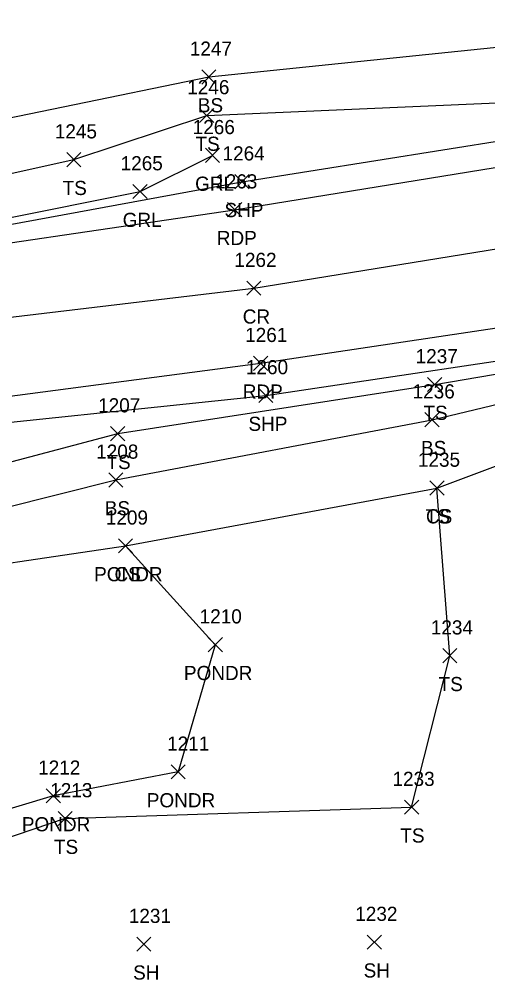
# Model space of a CAD drawing. Extents: x 1497084 to 1499861, y 734741 to 735567.
# Drawn here: x 1498420.9 to 1498487, y 735226.4 to 735362.1 of the extents above; entities that cross this region are included whole.
import ezdxf

# ---------------------------------------------------------------- set-up
doc = ezdxf.new("R2010")
doc.units = 0
for name, color, linetype in [('L_A', 7, 'Continuous'), ('L_I', 7, 'Continuous'), ('L_TIC', 7, 'Continuous'), ('LAWE', 7, 'Continuous'), ('LELB', 7, 'Continuous'), ('P_A', 7, 'Continuous'), ('P_I', 7, 'Continuous'), ('P_TIC', 7, 'Continuous'), ('PET', 7, 'Continuous'), ('PRC', 7, 'Continuous'), ('PSP', 7, 'Continuous'), ('R_A', 7, 'Continuous'), ('R_I', 7, 'Continuous'), ('R_TIC', 7, 'Continuous'), ('RGR', 7, 'Continuous')]:
    doc.layers.add(name, color=color, linetype=linetype)

msp = doc.modelspace()

# ---------------------------------------------------------------- linework, layer by layer
at = {"layer": 'L_TIC'}
for points in [[(1498446.67, 735352.97), (1498448.67, 735354.97)], [(1498448.67, 735352.97), (1498446.67, 735354.97)], [(1498446.37, 735347.53), (1498448.37, 735349.53)], [(1498448.37, 735347.53), (1498446.37, 735349.53)], [(1498427.62, 735341.29), (1498429.62, 735343.29)], [(1498429.62, 735341.29), (1498427.62, 735343.29)], [(1498478.54, 735309.53), (1498480.54, 735311.53)], [(1498480.54, 735309.53), (1498478.54, 735311.53)], [(1498478.17, 735304.56), (1498480.17, 735306.56)], [(1498480.17, 735304.56), (1498478.17, 735306.56)], [(1498433.81, 735302.59), (1498435.81, 735304.59)], [(1498435.81, 735302.59), (1498433.81, 735304.59)], [(1498433.54, 735296.05), (1498435.54, 735298.05)], [(1498435.54, 735296.05), (1498433.54, 735298.05)], [(1498478.86, 735294.91), (1498480.86, 735296.91)], [(1498480.86, 735294.91), (1498478.86, 735296.91)], [(1498478.86, 735294.91), (1498480.86, 735296.91)], [(1498480.86, 735294.91), (1498478.86, 735296.91)], [(1498434.91, 735286.74), (1498436.91, 735288.74)], [(1498436.91, 735286.74), (1498434.91, 735288.74)], [(1498434.91, 735286.74), (1498436.91, 735288.74)], [(1498436.91, 735286.74), (1498434.91, 735288.74)], [(1498447.58, 735272.78), (1498449.58, 735274.78)], [(1498449.58, 735272.78), (1498447.58, 735274.78)], [(1498480.68, 735271.22), (1498482.68, 735273.22)], [(1498482.68, 735271.22), (1498480.68, 735273.22)], [(1498442.34, 735254.81), (1498444.34, 735256.81)], [(1498444.34, 735254.81), (1498442.34, 735256.81)], [(1498424.71, 735251.42), (1498426.71, 735253.42)], [(1498426.71, 735251.42), (1498424.71, 735253.42)], [(1498475.28, 735249.83), (1498477.28, 735251.83)], [(1498477.28, 735249.83), (1498475.28, 735251.83)], [(1498426.4, 735248.23), (1498428.4, 735250.23)], [(1498428.4, 735248.23), (1498426.4, 735250.23)], [(1498426.4, 735248.23), (1498428.4, 735250.23)], [(1498428.4, 735248.23), (1498426.4, 735250.23)], [(1498437.5, 735230.48), (1498439.5, 735232.48)], [(1498439.5, 735230.48), (1498437.5, 735232.48)], [(1498470.02, 735230.77), (1498472.02, 735232.77)], [(1498472.02, 735230.77), (1498470.02, 735232.77)]]:
    msp.add_lwpolyline(points, dxfattribs=at)
at = {"layer": 'LAWE'}
msp.add_lwpolyline([(1498330.71, 735294.21), (1498340.7, 735295.58), (1498347.81, 735289.73), (1498355.83, 735283.8), (1498360.89, 735284.04), (1498388.96, 735276.52), (1498404.75, 735283.12), (1498435.91, 735287.74), (1498448.58, 735273.78), (1498443.34, 735255.81), (1498425.71, 735252.42), (1498412.05, 735248.32), (1498401.03, 735256.31), (1498395.49, 735265.65), (1498382.91, 735267.99), (1498367.49, 735259.74), (1498377.45, 735246.79), (1498383.14, 735228.32)], dxfattribs=at)
at = {"layer": 'LELB'}
for points in [[(1498337.56, 735327.03), (1498345.07, 735328.8), (1498360.02, 735336.05), (1498371.93, 735339.18), (1498383.26, 735341.12), (1498406.51, 735345.51), (1498447.67, 735353.97), (1498496.97, 735359.09), (1498555.39, 735373.27), (1498586.79, 735381.8), (1498595.75, 735372.64), (1498613.85, 735375.41), (1498671.76, 735381.92), (1498728.97, 735390.65), (1498788.67, 735399.74), (1498809.3, 735404.43), (1498807.97, 735434.2)], [(1498337.34, 735322.86), (1498344.97, 735324.75), (1498384.58, 735334.28), (1498409.2, 735337.4), (1498355.01, 735326.99), (1498382.45, 735331.79), (1498397.41, 735335.39), (1498428.62, 735342.29), (1498447.37, 735348.53), (1498497.98, 735350.74), (1498557.57, 735362.02), (1498577.34, 735369.5), (1498587.41, 735365.45), (1498611.95, 735369.89), (1498672.2, 735377.52), (1498729.57, 735386.75), (1498788.99, 735396.46), (1498814.15, 735401.69), (1498836.02, 735409.82), (1498851.62, 735410.69)], [(1498435.91, 735287.74), (1498479.86, 735295.91), (1498506.16, 735305.79), (1498562.09, 735310.28), (1498620.2, 735323.83), (1498678.14, 735331.24), (1498740.72, 735343.34), (1498795.48, 735350.02), (1498845.2, 735354.12), (1498873.2, 735358.8), (1498904.58, 735361.51), (1498941.92, 735355.1), (1499002.35, 735368.44), (1499018.4, 735380.28), (1499017.69, 735389.23)], [(1498348.47, 735290.66), (1498349.3, 735292.12), (1498356.63, 735290), (1498367.4, 735288.15), (1498383.02, 735293.44), (1498402.41, 735293.85), (1498412.25, 735297.62), (1498434.81, 735303.59), (1498479.54, 735310.53), (1498504.67, 735314.81), (1498560.97, 735322.47), (1498619.67, 735330.56), (1498677.12, 735338.58), (1498739.34, 735349.1), (1498794.83, 735357.09), (1498843.56, 735364.4), (1498863.08, 735369.39)], [(1498347.81, 735289.73), (1498349.19, 735291.09), (1498355.19, 735287.19), (1498360.89, 735284.04), (1498368.96, 735282.7), (1498386.86, 735285.14), (1498402.12, 735288.93), (1498434.54, 735297.05), (1498479.17, 735305.56), (1498505.43, 735311.83), (1498561.53, 735319.26), (1498619.71, 735327.6), (1498677.77, 735335.72), (1498739.77, 735346.92), (1498794.9, 735353.46), (1498843.96, 735361.06), (1498867.57, 735365.18)], [(1498427.4, 735249.23), (1498476.28, 735250.83), (1498481.68, 735272.22), (1498479.86, 735295.91)], [(1498427.4, 735249.23), (1498411.44, 735243.81), (1498399.46, 735253.36), (1498392.3, 735262.1), (1498383.66, 735264.94), (1498370.92, 735258.8), (1498380.93, 735247.98), (1498386.46, 735228.26)]]:
    msp.add_lwpolyline(points, dxfattribs=at)
at = {"layer": 'P_TIC'}
for points in [[(1498451.34, 735338.17), (1498453.34, 735340.17)], [(1498453.34, 735338.17), (1498451.34, 735340.17)], [(1498450.3, 735334.22), (1498452.3, 735336.22)], [(1498452.3, 735334.22), (1498450.3, 735336.22)], [(1498453.01, 735323.13), (1498455.01, 735325.13)], [(1498455.01, 735323.13), (1498453.01, 735325.13)], [(1498453.97, 735312.53), (1498455.97, 735314.53)], [(1498455.97, 735312.53), (1498453.97, 735314.53)], [(1498454.72, 735307.98), (1498456.72, 735309.98)], [(1498456.72, 735307.98), (1498454.72, 735309.98)]]:
    msp.add_lwpolyline(points, dxfattribs=at)
at = {"layer": 'PET'}
for points in [[(1498338.16, 735318.88), (1498357.92, 735321.69), (1498398.8, 735327.5), (1498451.3, 735335.22), (1498500.84, 735343.24), (1498558.12, 735351.59), (1498613.71, 735360.6), (1498673.07, 735369.22), (1498732.2, 735378.98), (1498789.96, 735387.82), (1498838.32, 735395.91), (1498888.99, 735404.3)], [(1498338.16, 735318.88), (1498339.87, 735308.1), (1498341.54, 735297.2), (1498360.21, 735300.18), (1498403.13, 735306.7), (1498454.97, 735313.53), (1498504.37, 735320.92), (1498560.62, 735329.11), (1498618.15, 735338.15), (1498676.47, 735346.79), (1498736.79, 735356.32), (1498793.85, 735365.14), (1498842.44, 735373.21), (1498892.67, 735381.87)]]:
    msp.add_lwpolyline(points, dxfattribs=at)
at = {"layer": 'PRC'}
msp.add_lwpolyline([(1498339.87, 735308.1), (1498359.7, 735310.92), (1498400.74, 735317.79), (1498454.01, 735324.13), (1498502.48, 735331.98), (1498559.28, 735340.31), (1498615.27, 735349.36), (1498674.88, 735357.8), (1498734.12, 735367.05), (1498791.71, 735376.05), (1498839.89, 735384.37), (1498890.74, 735392.79)], dxfattribs=at)
at = {"layer": 'PSP'}
for points in [[(1498357.92, 735321.69), (1498398.08, 735329.19), (1498452.34, 735339.17), (1498499.61, 735346.69), (1498557.87, 735356.09), (1498612.39, 735365.43), (1498672.54, 735374.02), (1498730.82, 735383.15), (1498789.68, 735392.14), (1498809.84, 735395.77), (1498833.8, 735399.85), (1498855.6, 735403.69)], [(1498360.21, 735300.18), (1498403.51, 735303.5), (1498455.72, 735308.98), (1498504.77, 735316.34), (1498560.61, 735324.72), (1498619.04, 735333.45), (1498677.11, 735341.57), (1498738.32, 735351.55), (1498794.38, 735360.63), (1498843.61, 735368.57), (1498860.46, 735371.23)]]:
    msp.add_lwpolyline(points, dxfattribs=at)
at = {"layer": 'R_TIC'}
for points in [[(1498447.19, 735341.89), (1498449.19, 735343.89)], [(1498449.19, 735341.89), (1498447.19, 735343.89)], [(1498436.96, 735336.78), (1498438.96, 735338.78)], [(1498438.96, 735336.78), (1498436.96, 735338.78)]]:
    msp.add_lwpolyline(points, dxfattribs=at)
at = {"layer": 'RGR'}
msp.add_lwpolyline([(1498338.33, 735319.53), (1498397.82, 735329.72), (1498437.96, 735337.78), (1498448.19, 735342.89)], dxfattribs=at)

# ---------------------------------------------------------------- texts
at = {"layer": 'L_A'}
for s, p in [('BS', (1498446.11, 735348.97)), ('TS', (1498445.78, 735343.53)), ('TS', (1498427.03, 735337.29)), ('TS', (1498477.95, 735305.53)), ('BS', (1498477.61, 735300.56)), ('TS', (1498433.22, 735298.59)), ('BS', (1498432.98, 735292.05)), ('TS', (1498478.27, 735290.91)), ('CS', (1498478.3, 735290.91)), ('PONDR', (1498431.48, 735282.74)), ('CS', (1498434.35, 735282.74)), ('PONDR', (1498444.15, 735268.78)), ('TS', (1498480.09, 735267.22)), ('PONDR', (1498438.91, 735250.81)), ('PONDR', (1498421.28, 735247.42)), ('TS', (1498474.69, 735245.83)), ('TS', (1498425.81, 735244.23)), ('TS', (1498425.81, 735244.23)), ('SH', (1498436.98, 735226.48)), ('SH', (1498469.51, 735226.77))]:
    msp.add_text(s, height=2, dxfattribs=at).set_placement(p)
at = {"layer": 'L_I'}
for s, p in [('1247', (1498444.98, 735356.97)), ('1246', (1498444.62, 735351.53)), ('1245', (1498425.93, 735345.29)), ('1237', (1498476.85, 735313.53)), ('1236', (1498476.42, 735308.56)), ('1207', (1498432.04, 735306.59)), ('1208', (1498431.77, 735300.05)), ('1235', (1498477.17, 735298.91)), ('1235', (1498477.17, 735298.91)), ('1209', (1498433.13, 735290.74)), ('1209', (1498433.13, 735290.74)), ('1210', (1498446.37, 735276.78)), ('1234', (1498478.99, 735275.22)), ('1211', (1498441.78, 735258.81)), ('1212', (1498423.58, 735255.42)), ('1233', (1498473.58, 735253.83)), ('1213', (1498425.28, 735252.23)), ('1213', (1498425.28, 735252.23)), ('1231', (1498436.37, 735234.48)), ('1232', (1498468.33, 735234.77))]:
    msp.add_text(s, height=2, dxfattribs=at).set_placement(p)
at = {"layer": 'P_A'}
for s, p in [('SHP', (1498449.88, 735334.17)), ('RDP', (1498448.79, 735330.22)), ('CR', (1498452.45, 735319.13)), ('RDP', (1498452.46, 735308.53)), ('SHP', (1498453.26, 735303.98))]:
    msp.add_text(s, height=2, dxfattribs=at).set_placement(p)
at = {"layer": 'P_I'}
for s, p in [('1264', (1498449.6, 735342.17)), ('1263', (1498448.56, 735338.22)), ('1262', (1498451.27, 735327.13)), ('1261', (1498452.79, 735316.53)), ('1260', (1498452.9, 735311.98))]:
    msp.add_text(s, height=2, dxfattribs=at).set_placement(p)
at = {"layer": 'R_A'}
for p in [(1498445.73, 735337.89), (1498435.51, 735332.78)]:
    msp.add_text('GRL', height=2, dxfattribs=at).set_placement(p)
at = {"layer": 'R_I'}
for s, p in [('1266', (1498445.39, 735345.89)), ('1265', (1498435.22, 735340.78))]:
    msp.add_text(s, height=2, dxfattribs=at).set_placement(p)

doc.saveas('drawing.dxf')
